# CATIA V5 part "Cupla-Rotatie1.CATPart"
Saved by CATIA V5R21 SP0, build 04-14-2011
Part number: Cupla R1
Bounding box of the stored display mesh (mm): x -100 to 100, y -99.803 to 99.803, z 0 to 700
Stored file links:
  C:\Users\MIRCEA\Desktop\PRRO\CATIAV5\Cupla-Rotatie1.CATPart
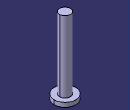
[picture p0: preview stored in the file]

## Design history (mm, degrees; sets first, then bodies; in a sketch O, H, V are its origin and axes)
Body1 (main body)
  Sketch1 on xy-plane, origin (0, 0, 0), H (1, 0, 0), V (0, 1, 0)
    circle A1 centre (0, 0) radius 50
    radius A1 = 50
  Pad1: profile Sketch1, direction (0, 0, 1), length 700
  Sketch2 on xy-plane, origin (0, 0, 0), H (1, 0, 0), V (0, 1, 0)
    circle A1 centre (0, 0) radius 100
    radius A1 = 100
  Pad2: profile Sketch2, direction (0, 0, 1), length 40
